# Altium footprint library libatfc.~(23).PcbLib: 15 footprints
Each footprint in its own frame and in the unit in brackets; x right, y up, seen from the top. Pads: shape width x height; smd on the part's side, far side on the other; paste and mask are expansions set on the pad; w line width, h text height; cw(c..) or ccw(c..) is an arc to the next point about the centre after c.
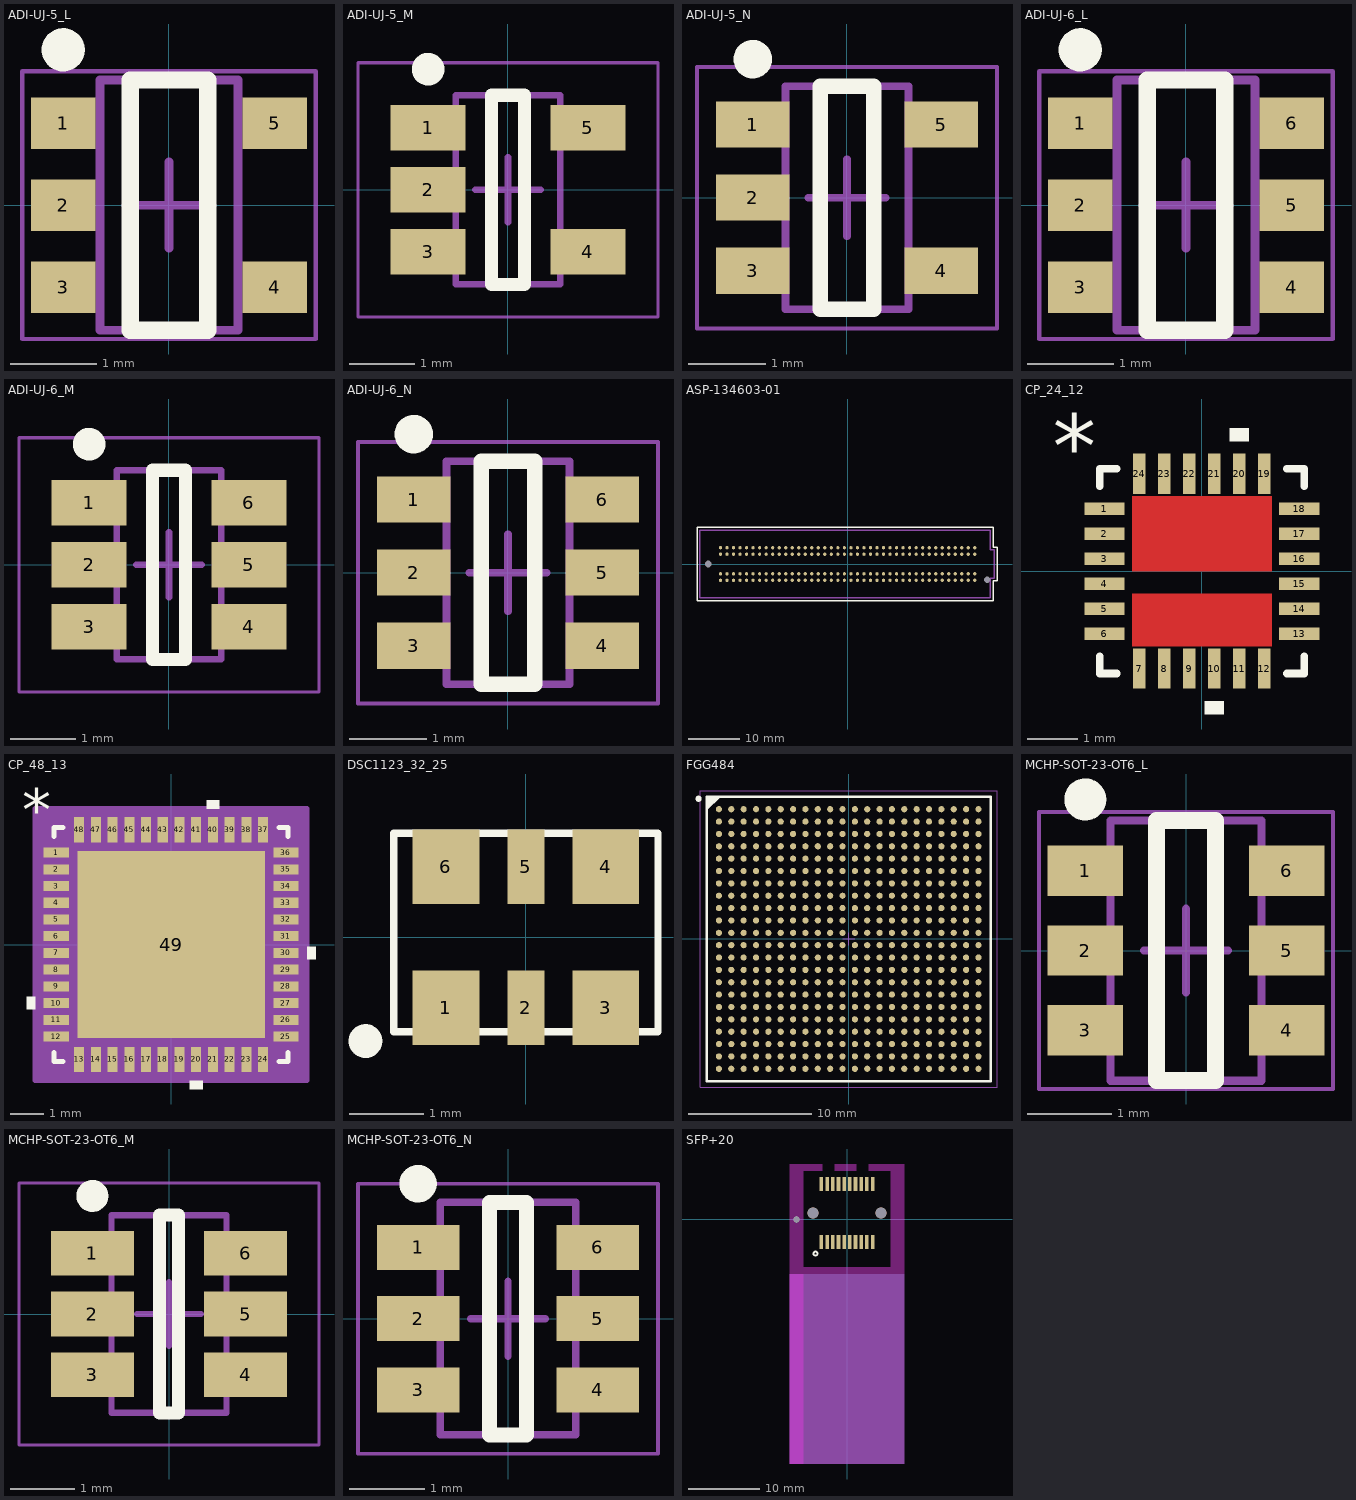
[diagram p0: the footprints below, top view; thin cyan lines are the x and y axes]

## ADI-UJ-5_L [mm] "SOT23, 5-Leads, Body 2.9x1.6mm, Pitch 0.95mm, IPC High Density"
height 1
pads (5):
  rect 0.75x0.6 smd: 1(-1.225,0.95) 2(-1.225,0) 3(-1.225,-0.95) 4(1.225,-0.95) 5(1.225,0.95)
Top Overlay:
  circle w0.25: c-1.225,1.8 r0.125
  lines w0.2: -0.45,-1.45 -0.45,1.45 0.45,1.45 0.45,-1.45 -0.45,-1.45
Mechanical 13:
  lines w0.1: -0.8,-1.45 0.8,-1.45 0.8,1.45 -0.8,1.45 -0.8,-1.45
Mechanical 15:
  lines w0.05: -1.7,-1.55 1.7,-1.55 1.7,1.55 -1.7,1.55 -1.7,-1.55
  lines w0.1: -0.5,0 0.5,0 ; 0,-0.5 0,0.5
3D body: height 1, standoff 0, extent -0.8,-1.45 0.8,1.45

## ADI-UJ-5_M [mm] "SOT23, 5-Leads, Body 2.9x1.6mm, Pitch 0.95mm, IPC Low Density"
height 1
pads (5):
  rect 1.15x0.7 smd: 1(-1.225,0.95) 2(-1.225,0) 3(-1.225,-0.95) 4(1.225,-0.95) 5(1.225,0.95)
Top Overlay:
  circle w0.25: c-1.225,1.85 r0.125
  lines w0.2: -0.25,-1.45 0.25,-1.45 0.25,1.45 -0.25,1.45 -0.25,-1.45
Mechanical 13:
  lines w0.1: -0.8,-1.45 -0.8,1.45 0.8,1.45 0.8,-1.45 -0.8,-1.45
Mechanical 15:
  lines w0.05: -2.3,-1.95 -2.3,1.95 2.3,1.95 2.3,-1.95 -2.3,-1.95
  lines w0.1: -0.5,0 0.5,0 ; 0,-0.5 0,0.5
3D body: height 1, standoff 0, extent -0.8,-1.45 0.8,1.45

## ADI-UJ-5_N [mm] "SOT23, 5-Leads, Body 2.9x1.6mm, Pitch 0.95mm, IPC Medium Density"
height 1
pads (5):
  rect 0.95x0.6 smd: 1(-1.225,0.95) 2(-1.225,0) 3(-1.225,-0.95) 4(1.225,-0.95) 5(1.225,0.95)
Top Overlay:
  circle w0.25: c-1.225,1.8 r0.125
  lines w0.2: -0.35,-1.45 -0.35,1.45 0.35,1.45 0.35,-1.45 -0.35,-1.45
Mechanical 13:
  lines w0.1: -0.8,-1.45 0.8,-1.45 0.8,1.45 -0.8,1.45 -0.8,-1.45
Mechanical 15:
  lines w0.05: -1.95,-1.7 1.95,-1.7 1.95,1.7 -1.95,1.7 -1.95,-1.7
  lines w0.1: -0.5,0 0.5,0 ; 0,-0.5 0,0.5
3D body: height 1, standoff 0, extent -0.8,-1.45 0.8,1.45

## ADI-UJ-6_L [mm] "SOT23, 6-Leads, Body 2.9x1.6mm, Pitch 0.95mm, IPC High Density"
height 1
pads (6):
  rect 0.75x0.6 smd: 1(-1.225,0.95) 2(-1.225,0) 3(-1.225,-0.95) 4(1.225,-0.95) 5(1.225,0) 6(1.225,0.95)
Top Overlay:
  circle w0.25: c-1.225,1.8 r0.125
  lines w0.2: -0.45,-1.45 0.45,-1.45 0.45,1.45 -0.45,1.45 -0.45,-1.45
Mechanical 13:
  lines w0.1: -0.8,-1.45 -0.8,1.45 0.8,1.45 0.8,-1.45 -0.8,-1.45
Mechanical 15:
  lines w0.05: -1.7,-1.55 -1.7,1.55 1.7,1.55 1.7,-1.55 -1.7,-1.55
  lines w0.1: -0.5,0 0.5,0 ; 0,-0.5 0,0.5
3D body: height 1, standoff 0.1, extent -0.8,-1.45 0.8,1.45

## ADI-UJ-6_M [mm] "SOT23, 6-Leads, Body 2.9x1.6mm, Pitch 0.95mm, IPC Low Density"
height 1
pads (6):
  rect 1.15x0.7 smd: 1(-1.225,0.95) 2(-1.225,0) 3(-1.225,-0.95) 4(1.225,-0.95) 5(1.225,0) 6(1.225,0.95)
Top Overlay:
  circle w0.25: c-1.225,1.85 r0.125
  lines w0.2: -0.25,-1.45 -0.25,1.45 0.25,1.45 0.25,-1.45 -0.25,-1.45
Mechanical 13:
  lines w0.1: -0.8,-1.45 0.8,-1.45 0.8,1.45 -0.8,1.45 -0.8,-1.45
Mechanical 15:
  lines w0.05: -2.3,-1.95 2.3,-1.95 2.3,1.95 -2.3,1.95 -2.3,-1.95
  lines w0.1: -0.5,0 0.5,0 ; 0,-0.5 0,0.5
3D body: height 1, standoff 0.1, extent -0.8,-1.45 0.8,1.45

## ADI-UJ-6_N [mm] "SOT23, 6-Leads, Body 2.9x1.6mm, Pitch 0.95mm, IPC Medium Density"
height 1
pads (6):
  rect 0.95x0.6 smd: 1(-1.225,0.95) 2(-1.225,0) 3(-1.225,-0.95) 4(1.225,-0.95) 5(1.225,0) 6(1.225,0.95)
Top Overlay:
  circle w0.25: c-1.225,1.8 r0.125
  lines w0.2: -0.35,-1.45 0.35,-1.45 0.35,1.45 -0.35,1.45 -0.35,-1.45
Mechanical 13:
  lines w0.1: -0.8,-1.45 -0.8,1.45 0.8,1.45 0.8,-1.45 -0.8,-1.45
Mechanical 15:
  lines w0.05: -1.95,-1.7 -1.95,1.7 1.95,1.7 1.95,-1.7 -1.95,-1.7
  lines w0.1: -0.5,0 0.5,0 ; 0,-0.5 0,0.5
3D body: height 1, standoff 0.1, extent -0.8,-1.45 0.8,1.45

## ASP-134603-01 [mil]
pads (162):
  round 25 smd paste+5 mask+2: C1(975,-125) C2(925,-125) C3(875,-125) C4(825,-125) C5(775,-125) C6(725,-125) C7(675,-125) C8(625,-125) C9(575,-125) C10(525,-125) C11(475,-125) C12(425,-125) C13(375,-125) C14(325,-125) C15(275,-125) C16(225,-125) C17(175,-125) C18(125,-125) C19(75,-125) C20(25,-125) C21(-25,-125) C22(-75,-125) C23(-125,-125) C24(-175,-125) C25(-225,-125) C26(-275,-125) C27(-325,-125) C28(-375,-125) C29(-425,-125) C30(-475,-125) C31(-525,-125) C32(-575,-125) C33(-625,-125) C34(-675,-125) C35(-725,-125) C36(-775,-125) C37(-825,-125) C38(-875,-125) C39(-925,-125) C40(-975,-125) D1(975,-75) D2(925,-75) D3(875,-75) D4(825,-75) D5(775,-75) D6(725,-75) D7(675,-75) D8(625,-75) D9(575,-75) D10(525,-75) D11(475,-75) D12(425,-75) D13(375,-75) D14(325,-75) D15(275,-75) D16(225,-75) D17(175,-75) D18(125,-75) D19(75,-75) D20(25,-75) D21(-25,-75) D22(-75,-75) D23(-125,-75) D24(-175,-75) D25(-225,-75) D26(-275,-75) D27(-325,-75) D28(-375,-75) D29(-425,-75) D30(-475,-75) D31(-525,-75) D32(-575,-75) D33(-625,-75) D34(-675,-75) D35(-725,-75) D36(-775,-75) D37(-825,-75) D38(-875,-75) D39(-925,-75) D40(-975,-75) G1(975,75) G2(925,75) G3(875,75) G4(825,75) G5(775,75) G6(725,75) G7(675,75) G8(625,75) G9(575,75) G10(525,75) G11(475,75) G12(425,75) G13(375,75) G14(325,75) G15(275,75) G16(225,75) G17(175,75) G18(125,75) G19(75,75) G20(25,75) G21(-25,75) G22(-75,75) G23(-125,75) G24(-175,75) G25(-225,75) G26(-275,75) G27(-325,75) G28(-375,75) G29(-425,75) G30(-475,75) G31(-525,75) G32(-575,75) G33(-625,75) G34(-675,75) G35(-725,75) G36(-775,75) G37(-825,75) G38(-875,75) G39(-925,75) G40(-975,75) H1(975,125) H2(925,125) H3(875,125) H4(825,125) H5(775,125) H6(725,125) H7(675,125) H8(625,125) H9(575,125) H10(525,125) H11(475,125) H12(425,125) H13(375,125) H14(325,125) H15(275,125) H16(225,125) H17(175,125) H18(125,125) H19(75,125) H20(25,125) H21(-25,125) H22(-75,125) H23(-125,125) H24(-175,125) H25(-225,125) H26(-275,125) H27(-325,125) H28(-375,125) H29(-425,125) H30(-475,125) H31(-525,125) H32(-575,125) H33(-625,125) H34(-675,125) H35(-725,125) H36(-775,125) H37(-825,125) H38(-875,125) H39(-925,125) H40(-975,125)
  round 0 hole 50 unplated: MH1(1070.5,-120) MH2(-1070.5,0)
Top Overlay:
  lines w10: -1155,-280 1115,-280 1115,-130 1145,-130 1145,130 1115,130 1115,280 -1155,280 -1155,-280
Mechanical 1:
  lines w10: -1135,-260 1095,-260 1095,-110 1125,-110 1125,110 1095,110 1095,260 -1135,260 -1135,-260
  text "J1" at -19.57,-20 h30
3D body "459714305.stp": height 259.15, standoff -48.85, extent -1131,-295 1151,283

## CP_24_12 [mm]
pads (24):
  rect 0.805x0.25 smd: 1(-1.952,1.25) 2(-1.952,0.75) 3(-1.952,0.25) 4(-1.952,-0.25) 5(-1.952,-0.75) 6(-1.952,-1.25) 13(1.952,-1.25) 14(1.952,-0.75) 15(1.952,-0.25) 16(1.952,0.25) 17(1.952,0.75) 18(1.952,1.25)
  rect 0.25x0.805 smd: 7(-1.25,-1.952) 8(-0.75,-1.952) 9(-0.25,-1.952) 10(0.25,-1.952) 11(0.75,-1.952) 12(1.25,-1.952) 19(1.25,1.952) 20(0.75,1.952) 21(0.25,1.952) 22(-0.25,1.952) 23(-0.75,1.952) 24(-1.25,1.952)
Top Layer:
  region: -1.4,0 -1.4,1.5 1.4,1.5 1.4,0
  region: -1.4,-1.5 -1.4,-0.45 1.4,-0.45 1.4,-1.5
Top Overlay:
  region: 0.44,-2.609 0.059,-2.609 0.059,-2.863 0.44,-2.863
  region: 0.941,2.609 0.56,2.609 0.56,2.863 0.941,2.863
  lines w0.152: -2.05,-1.708 -2.05,-2.05 -1.708,-2.05 ; -2.05,1.708 -2.05,2.05 -1.708,2.05 ; 1.708,-2.05 2.05,-2.05 2.05,-1.708 ; 1.708,2.05 2.05,2.05 2.05,1.708
  text "*" at -2.99,1.881 h1.27
Top Paste:
  region: -1.4,0 -1.4,1.5 1.4,1.5 1.4,0
  region: -1.4,-1.5 -1.4,-0.45 1.4,-0.45 1.4,-1.5
Top Solder:
  region: -1.4,0 -1.4,1.5 1.4,1.5 1.4,0
  region: -1.4,-1.5 -1.4,-0.45 1.4,-0.45 1.4,-1.5
Mechanical 13:
  text "*" at -2.99,1.881 h1.27
3D body: height 0.25, standoff 0, extent 0,0 0.254,0.254

## CP_48_13 [mm]
pads (49):
  rect 0.755x0.3 smd: 1(-3.433,2.75) 2(-3.433,2.25) 3(-3.433,1.75) 4(-3.433,1.25) 5(-3.433,0.75) 6(-3.433,0.25) 7(-3.433,-0.25) 8(-3.433,-0.75) 9(-3.433,-1.25) 10(-3.433,-1.75) 11(-3.433,-2.25) 12(-3.433,-2.75) 25(3.433,-2.75) 26(3.433,-2.25) 27(3.433,-1.75) 28(3.433,-1.25) 29(3.433,-0.75) 30(3.433,-0.25) 31(3.433,0.25) 32(3.433,0.75) 33(3.433,1.25) 34(3.433,1.75) 35(3.433,2.25) 36(3.433,2.75)
  rect 0.3x0.755 smd: 13(-2.75,-3.433) 14(-2.25,-3.433) 15(-1.75,-3.433) 16(-1.25,-3.433) 17(-0.75,-3.433) 18(-0.25,-3.433) 19(0.25,-3.433) 20(0.75,-3.433) 21(1.25,-3.433) 22(1.75,-3.433) 23(2.25,-3.433) 24(2.75,-3.433) 37(2.75,3.433) 38(2.25,3.433) 39(1.75,3.433) 40(1.25,3.433) 41(0.75,3.433) 42(0.25,3.433) 43(-0.25,3.433) 44(-0.75,3.433) 45(-1.25,3.433) 46(-1.75,3.433) 47(-2.25,3.433) 48(-2.75,3.433)
  rect 5.6x5.6 smd mask-2.781: 49(0,0)
Top Overlay:
  region: -4.064,-1.559 -4.318,-1.559 -4.318,-1.94 -4.064,-1.94
  region: 0.941,-4.064 0.56,-4.064 0.56,-4.318 0.941,-4.318
  region: 4.064,-0.059 4.318,-0.059 4.318,-0.44 4.064,-0.44
  region: 1.441,4.064 1.06,4.064 1.06,4.318 1.441,4.318
  lines w0.152: -3.5,-3.233 -3.5,-3.5 -3.233,-3.5 ; -3.5,3.233 -3.5,3.5 -3.233,3.5 ; 3.233,-3.5 3.5,-3.5 3.5,-3.233 ; 3.233,3.5 3.5,3.5 3.5,3.233
  text "*" at -4.445,3.381 h1.27
Mechanical 13:
  text "*" at -4.445,3.381 h1.27
Mechanical 15:
  region: 4.064,-4.064 -4.064,-4.064 -4.064,4.064 4.064,4.064
  lines w0.152: -4.064,-4.064 -4.064,4.064 4.064,4.064 4.064,-4.064 -4.064,-4.064
3D body: height 0.25, standoff 0, extent 0,0 0.254,0.254

## DSC1123_32_25 [mm]
pads (6):
  rect 0.9x1 smd: 1(-1.075,-0.95) 3(1.075,-0.95) 4(1.075,0.95) 6(-1.075,0.95)
  rect 0.5x1 smd: 2(0,-0.95) 5(0,0.95)
Top Overlay:
  circle w0.254: c-2.159,-1.397 r0.1
  lines w0.1: -1.778,-1.27 1.778,-1.27 1.778,1.397 -1.778,1.397 -1.778,-1.27
3D body: height 0.85, standoff 0, extent -1.778,-1.27 1.778,1.397

## FGG484 [mm] "BGA, 484-Balls, Body 23x23mm, Pitch 1mm"
height 2.6
pads (484):
  round 0.5 smd: A1(-10.5,10.5) A2(-9.5,10.5) A3(-8.5,10.5) A4(-7.5,10.5) A5(-6.5,10.5) A6(-5.5,10.5) A7(-4.5,10.5) A8(-3.5,10.5) A9(-2.5,10.5) A10(-1.5,10.5) A11(-0.5,10.5) A12(0.5,10.5) A13(1.5,10.5) A14(2.5,10.5) A15(3.5,10.5) A16(4.5,10.5) A17(5.5,10.5) A18(6.5,10.5) A19(7.5,10.5) A20(8.5,10.5) A21(9.5,10.5) A22(10.5,10.5) AA1(-10.5,-9.5) AA2(-9.5,-9.5) AA3(-8.5,-9.5) AA4(-7.5,-9.5) AA5(-6.5,-9.5) AA6(-5.5,-9.5) AA7(-4.5,-9.5) AA8(-3.5,-9.5) AA9(-2.5,-9.5) AA10(-1.5,-9.5) AA11(-0.5,-9.5) AA12(0.5,-9.5) AA13(1.5,-9.5) AA14(2.5,-9.5) AA15(3.5,-9.5) AA16(4.5,-9.5) AA17(5.5,-9.5) AA18(6.5,-9.5) AA19(7.5,-9.5) AA20(8.5,-9.5) AA21(9.5,-9.5) AA22(10.5,-9.5) AB1(-10.5,-10.5) AB2(-9.5,-10.5) AB3(-8.5,-10.5) AB4(-7.5,-10.5) AB5(-6.5,-10.5) AB6(-5.5,-10.5) AB7(-4.5,-10.5) AB8(-3.5,-10.5) AB9(-2.5,-10.5) AB10(-1.5,-10.5) AB11(-0.5,-10.5) AB12(0.5,-10.5) AB13(1.5,-10.5) AB14(2.5,-10.5) AB15(3.5,-10.5) AB16(4.5,-10.5) AB17(5.5,-10.5) AB18(6.5,-10.5) AB19(7.5,-10.5) AB20(8.5,-10.5) AB21(9.5,-10.5) AB22(10.5,-10.5) B1(-10.5,9.5) B2(-9.5,9.5) B3(-8.5,9.5) B4(-7.5,9.5) B5(-6.5,9.5) B6(-5.5,9.5) B7(-4.5,9.5) B8(-3.5,9.5) B9(-2.5,9.5) B10(-1.5,9.5) B11(-0.5,9.5) B12(0.5,9.5) B13(1.5,9.5) B14(2.5,9.5) B15(3.5,9.5) B16(4.5,9.5) B17(5.5,9.5) B18(6.5,9.5) B19(7.5,9.5) B20(8.5,9.5) B21(9.5,9.5) B22(10.5,9.5) C1(-10.5,8.5) C2(-9.5,8.5) C3(-8.5,8.5) C4(-7.5,8.5) C5(-6.5,8.5) C6(-5.5,8.5) C7(-4.5,8.5) C8(-3.5,8.5) C9(-2.5,8.5) C10(-1.5,8.5) C11(-0.5,8.5) C12(0.5,8.5) C13(1.5,8.5) C14(2.5,8.5) C15(3.5,8.5) C16(4.5,8.5) C17(5.5,8.5) C18(6.5,8.5) C19(7.5,8.5) C20(8.5,8.5) C21(9.5,8.5) C22(10.5,8.5) D1(-10.5,7.5) D2(-9.5,7.5) D3(-8.5,7.5) D4(-7.5,7.5) D5(-6.5,7.5) D6(-5.5,7.5) D7(-4.5,7.5) D8(-3.5,7.5) D9(-2.5,7.5) D10(-1.5,7.5) D11(-0.5,7.5) D12(0.5,7.5) D13(1.5,7.5) D14(2.5,7.5) D15(3.5,7.5) D16(4.5,7.5) D17(5.5,7.5) D18(6.5,7.5) D19(7.5,7.5) D20(8.5,7.5) D21(9.5,7.5) D22(10.5,7.5) E1(-10.5,6.5) E2(-9.5,6.5) E3(-8.5,6.5) E4(-7.5,6.5) E5(-6.5,6.5) E6(-5.5,6.5) E7(-4.5,6.5) E8(-3.5,6.5) E9(-2.5,6.5) E10(-1.5,6.5) E11(-0.5,6.5) E12(0.5,6.5) E13(1.5,6.5) E14(2.5,6.5) E15(3.5,6.5) E16(4.5,6.5) E17(5.5,6.5) E18(6.5,6.5) E19(7.5,6.5) E20(8.5,6.5) E21(9.5,6.5) E22(10.5,6.5) F1(-10.5,5.5) F2(-9.5,5.5) F3(-8.5,5.5) F4(-7.5,5.5) F5(-6.5,5.5) F6(-5.5,5.5) F7(-4.5,5.5) F8(-3.5,5.5) F9(-2.5,5.5) F10(-1.5,5.5) F11(-0.5,5.5) F12(0.5,5.5) F13(1.5,5.5) F14(2.5,5.5) F15(3.5,5.5) F16(4.5,5.5) F17(5.5,5.5) F18(6.5,5.5) F19(7.5,5.5) F20(8.5,5.5) F21(9.5,5.5) F22(10.5,5.5) G1(-10.5,4.5) G2(-9.5,4.5) G3(-8.5,4.5) G4(-7.5,4.5) G5(-6.5,4.5) G6(-5.5,4.5) G7(-4.5,4.5) G8(-3.5,4.5) G9(-2.5,4.5) G10(-1.5,4.5) G11(-0.5,4.5) G12(0.5,4.5) G13(1.5,4.5) G14(2.5,4.5) G15(3.5,4.5) G16(4.5,4.5) G17(5.5,4.5) G18(6.5,4.5) G19(7.5,4.5) G20(8.5,4.5) G21(9.5,4.5) G22(10.5,4.5) H1(-10.5,3.5) H2(-9.5,3.5) H3(-8.5,3.5) H4(-7.5,3.5) H5(-6.5,3.5) H6(-5.5,3.5) H7(-4.5,3.5) H8(-3.5,3.5) H9(-2.5,3.5) H10(-1.5,3.5) H11(-0.5,3.5) H12(0.5,3.5) H13(1.5,3.5) H14(2.5,3.5) H15(3.5,3.5) H16(4.5,3.5) H17(5.5,3.5) H18(6.5,3.5) H19(7.5,3.5) H20(8.5,3.5) H21(9.5,3.5) H22(10.5,3.5) J1(-10.5,2.5) J2(-9.5,2.5) J3(-8.5,2.5) J4(-7.5,2.5) J5(-6.5,2.5) J6(-5.5,2.5) J7(-4.5,2.5) J8(-3.5,2.5) J9(-2.5,2.5) J10(-1.5,2.5) J11(-0.5,2.5) J12(0.5,2.5) J13(1.5,2.5) J14(2.5,2.5) J15(3.5,2.5) J16(4.5,2.5) J17(5.5,2.5) J18(6.5,2.5) J19(7.5,2.5) J20(8.5,2.5) J21(9.5,2.5) J22(10.5,2.5) K1(-10.5,1.5) K2(-9.5,1.5) K3(-8.5,1.5) K4(-7.5,1.5) K5(-6.5,1.5) K6(-5.5,1.5) K7(-4.5,1.5) K8(-3.5,1.5) K9(-2.5,1.5) K10(-1.5,1.5) K11(-0.5,1.5) K12(0.5,1.5) K13(1.5,1.5) K14(2.5,1.5) K15(3.5,1.5) K16(4.5,1.5) K17(5.5,1.5) K18(6.5,1.5) K19(7.5,1.5) K20(8.5,1.5) K21(9.5,1.5) K22(10.5,1.5) L1(-10.5,0.5) L2(-9.5,0.5) L3(-8.5,0.5) L4(-7.5,0.5) L5(-6.5,0.5) L6(-5.5,0.5) L7(-4.5,0.5) L8(-3.5,0.5) L9(-2.5,0.5) L10(-1.5,0.5) L11(-0.5,0.5) L12(0.5,0.5) L13(1.5,0.5) L14(2.5,0.5) L15(3.5,0.5) L16(4.5,0.5) L17(5.5,0.5) L18(6.5,0.5) L19(7.5,0.5) L20(8.5,0.5) L21(9.5,0.5) L22(10.5,0.5) M1(-10.5,-0.5) M2(-9.5,-0.5) M3(-8.5,-0.5) M4(-7.5,-0.5) M5(-6.5,-0.5) M6(-5.5,-0.5) M7(-4.5,-0.5) M8(-3.5,-0.5) M9(-2.5,-0.5) M10(-1.5,-0.5) M11(-0.5,-0.5) M12(0.5,-0.5) M13(1.5,-0.5) M14(2.5,-0.5) M15(3.5,-0.5) M16(4.5,-0.5) M17(5.5,-0.5) M18(6.5,-0.5) M19(7.5,-0.5) M20(8.5,-0.5) M21(9.5,-0.5) M22(10.5,-0.5) N1(-10.5,-1.5) N2(-9.5,-1.5) N3(-8.5,-1.5) N4(-7.5,-1.5) N5(-6.5,-1.5) N6(-5.5,-1.5) N7(-4.5,-1.5) N8(-3.5,-1.5) N9(-2.5,-1.5) N10(-1.5,-1.5) N11(-0.5,-1.5) N12(0.5,-1.5) N13(1.5,-1.5) N14(2.5,-1.5) N15(3.5,-1.5) N16(4.5,-1.5) N17(5.5,-1.5) N18(6.5,-1.5) N19(7.5,-1.5) N20(8.5,-1.5) N21(9.5,-1.5) N22(10.5,-1.5) P1(-10.5,-2.5) P2(-9.5,-2.5) P3(-8.5,-2.5) P4(-7.5,-2.5) P5(-6.5,-2.5) P6(-5.5,-2.5) P7(-4.5,-2.5) P8(-3.5,-2.5) P9(-2.5,-2.5) P10(-1.5,-2.5) P11(-0.5,-2.5) P12(0.5,-2.5) P13(1.5,-2.5) P14(2.5,-2.5) P15(3.5,-2.5) P16(4.5,-2.5) P17(5.5,-2.5) P18(6.5,-2.5) P19(7.5,-2.5) P20(8.5,-2.5) P21(9.5,-2.5) P22(10.5,-2.5) R1(-10.5,-3.5) R2(-9.5,-3.5) R3(-8.5,-3.5) R4(-7.5,-3.5) R5(-6.5,-3.5) R6(-5.5,-3.5) R7(-4.5,-3.5) R8(-3.5,-3.5) R9(-2.5,-3.5) R10(-1.5,-3.5) R11(-0.5,-3.5) R12(0.5,-3.5) R13(1.5,-3.5) R14(2.5,-3.5) R15(3.5,-3.5) R16(4.5,-3.5) R17(5.5,-3.5) R18(6.5,-3.5) R19(7.5,-3.5) R20(8.5,-3.5) R21(9.5,-3.5) R22(10.5,-3.5) T1(-10.5,-4.5) T2(-9.5,-4.5) T3(-8.5,-4.5) T4(-7.5,-4.5) T5(-6.5,-4.5) T6(-5.5,-4.5) T7(-4.5,-4.5) T8(-3.5,-4.5) T9(-2.5,-4.5) T10(-1.5,-4.5) T11(-0.5,-4.5) T12(0.5,-4.5) T13(1.5,-4.5) T14(2.5,-4.5) T15(3.5,-4.5) T16(4.5,-4.5) T17(5.5,-4.5) T18(6.5,-4.5) T19(7.5,-4.5) T20(8.5,-4.5) T21(9.5,-4.5) T22(10.5,-4.5) U1(-10.5,-5.5) U2(-9.5,-5.5) U3(-8.5,-5.5) U4(-7.5,-5.5) U5(-6.5,-5.5) U6(-5.5,-5.5) U7(-4.5,-5.5) U8(-3.5,-5.5) U9(-2.5,-5.5) U10(-1.5,-5.5) U11(-0.5,-5.5) U12(0.5,-5.5) U13(1.5,-5.5) U14(2.5,-5.5) U15(3.5,-5.5) U16(4.5,-5.5) U17(5.5,-5.5) U18(6.5,-5.5) U19(7.5,-5.5) U20(8.5,-5.5) U21(9.5,-5.5) U22(10.5,-5.5) V1(-10.5,-6.5) V2(-9.5,-6.5) V3(-8.5,-6.5) V4(-7.5,-6.5) V5(-6.5,-6.5) V6(-5.5,-6.5) V7(-4.5,-6.5) V8(-3.5,-6.5) V9(-2.5,-6.5) V10(-1.5,-6.5) V11(-0.5,-6.5) V12(0.5,-6.5) V13(1.5,-6.5) V14(2.5,-6.5) V15(3.5,-6.5) V16(4.5,-6.5) V17(5.5,-6.5) V18(6.5,-6.5) V19(7.5,-6.5) V20(8.5,-6.5) V21(9.5,-6.5) V22(10.5,-6.5) W1(-10.5,-7.5) W2(-9.5,-7.5) W3(-8.5,-7.5) W4(-7.5,-7.5) W5(-6.5,-7.5) W6(-5.5,-7.5) W7(-4.5,-7.5) W8(-3.5,-7.5) W9(-2.5,-7.5) W10(-1.5,-7.5) W11(-0.5,-7.5) W12(0.5,-7.5) W13(1.5,-7.5) W14(2.5,-7.5) W15(3.5,-7.5) W16(4.5,-7.5) W17(5.5,-7.5) W18(6.5,-7.5) W19(7.5,-7.5) W20(8.5,-7.5) W21(9.5,-7.5) W22(10.5,-7.5) Y1(-10.5,-8.5) Y2(-9.5,-8.5) Y3(-8.5,-8.5) Y4(-7.5,-8.5) Y5(-6.5,-8.5) Y6(-5.5,-8.5) Y7(-4.5,-8.5) Y8(-3.5,-8.5) Y9(-2.5,-8.5) Y10(-1.5,-8.5) Y11(-0.5,-8.5) Y12(0.5,-8.5) Y13(1.5,-8.5) Y14(2.5,-8.5) Y15(3.5,-8.5) Y16(4.5,-8.5) Y17(5.5,-8.5) Y18(6.5,-8.5) Y19(7.5,-8.5) Y20(8.5,-8.5) Y21(9.5,-8.5) Y22(10.5,-8.5)
Top Overlay:
  circle w0.25: c-12.15,11.35 r0.125
  region: -10.5,11.5 -11.5,10.5 -11.5,11.5
  lines w0.2: -11.5,10.5 -10.5,11.5 ; -11.5,-11.5 -11.5,11.5 11.5,11.5 11.5,-11.5 -11.5,-11.5
Mechanical 13:
  lines w0.1: -11.5,-11.5 -11.5,11.5 11.5,11.5 11.5,-11.5 -11.5,-11.5
Mechanical 15:
  lines w0.05: -12,-12 -12,12 12,12 12,-12 -12,-12
  lines w0.1: -0.5,0 0.5,0 ; 0,-0.5 0,0.5
3D body: height 2.6, standoff 0.35, extent -11.5,-11.5 11.5,11.5

## MCHP-SOT-23-OT6_L [mm] "SOT23, 6-Leads, Body 2.9x1.55mm, Pitch 0.95mm, IPC High Density"
height 1.45
pads (6):
  rect 0.9x0.6 smd: 1(-1.2,0.95) 2(-1.2,0) 3(-1.2,-0.95) 4(1.2,-0.95) 5(1.2,0) 6(1.2,0.95)
Top Overlay:
  circle w0.25: c-1.2,1.8 r0.125
  lines w0.2: -0.35,-1.55 0.35,-1.55 0.35,1.55 -0.35,1.55 -0.35,-1.55
Mechanical 13:
  lines w0.1: -0.9,-1.55 -0.9,1.55 0.9,1.55 0.9,-1.55 -0.9,-1.55
Mechanical 15:
  lines w0.05: -1.75,-1.65 -1.75,1.65 1.75,1.65 1.75,-1.65 -1.75,-1.65
  lines w0.1: -0.5,0 0.5,0 ; 0,-0.5 0,0.5
3D body: height 1.45, standoff 0, extent -0.9,-1.55 0.9,1.55

## MCHP-SOT-23-OT6_M [mm] "SOT23, 6-Leads, Body 2.9x1.55mm, Pitch 0.95mm, IPC Low Density"
height 1.45
pads (6):
  rect 1.3x0.7 smd: 1(-1.2,0.95) 2(-1.2,0) 3(-1.2,-0.95) 4(1.2,-0.95) 5(1.2,0) 6(1.2,0.95)
Top Overlay:
  circle w0.25: c-1.2,1.85 r0.125
  lines w0.2: -0.15,-1.55 0.15,-1.55 0.15,1.55 -0.15,1.55 -0.15,-1.55
Mechanical 13:
  lines w0.1: -0.9,-1.55 -0.9,1.55 0.9,1.55 0.9,-1.55 -0.9,-1.55
Mechanical 15:
  lines w0.05: -2.35,-2.05 -2.35,2.05 2.35,2.05 2.35,-2.05 -2.35,-2.05
  lines w0.1: -0.5,0 0.5,0 ; 0,-0.5 0,0.5
3D body: height 1.45, standoff 0, extent -0.9,-1.55 0.9,1.55

## MCHP-SOT-23-OT6_N [mm] "SOT23, 6-Leads, Body 2.9x1.55mm, Pitch 0.95mm, IPC Medium Density"
height 1.45
pads (6):
  rect 1.1x0.6 smd: 1(-1.2,0.95) 2(-1.2,0) 3(-1.2,-0.95) 4(1.2,-0.95) 5(1.2,0) 6(1.2,0.95)
Top Overlay:
  circle w0.25: c-1.2,1.8 r0.125
  lines w0.2: -0.25,-1.55 -0.25,1.55 0.25,1.55 0.25,-1.55 -0.25,-1.55
Mechanical 13:
  lines w0.1: -0.9,-1.55 0.9,-1.55 0.9,1.55 -0.9,1.55 -0.9,-1.55
Mechanical 15:
  lines w0.05: -2,-1.8 2,-1.8 2,1.8 -2,1.8 -2,-1.8
  lines w0.1: -0.5,0 0.5,0 ; 0,-0.5 0,0.5
3D body: height 1.45, standoff 0, extent -0.9,-1.55 0.9,1.55

## SFP+20 [mm]
pads (23):
  rect 0.5x2 smd: 1(-3.6,-3.2) 2(-2.8,-3.2) 3(-2,-3.2) 4(-1.2,-3.2) 5(-0.4,-3.2) 6(0.4,-3.2) 7(1.2,-3.2) 8(2,-3.2) 9(2.8,-3.2) 10(3.6,-3.2) 11(3.6,5) 12(2.8,5) 13(2,5) 14(1.2,5) 15(0.4,5) 16(-0.4,5) 17(-1.2,5) 18(-2,5) 19(-2.8,5) 20(-3.6,5)
  round 0.85 hole 0.85 paste+0 mask+0: ""(-7.13,0)
  round 1.55 hole 1.55 paste+0 mask+0: ""(-4.8,0.9) ""(4.8,0.9)
Top Overlay:
  circle w0.254: c-4.445,-4.826 r0.284
Keep-Out Layer:
  rectangle: 3.05,6.8 8.12,7.8
  rectangle: -8.13,6.8 -3.45,7.8
  rectangle: -8.13,-7.7 8.13,-6.7
  rectangle: -1.75,6.8 1.35,7.8
Keep-Out Layer:
  rectangle: 6.13,-7.7 8.12,7.8
  rectangle: -8.13,-34.5 -6.13,7.8
Mechanical 1:
  rectangle: -8.13,-34.5 8.12,-7.7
